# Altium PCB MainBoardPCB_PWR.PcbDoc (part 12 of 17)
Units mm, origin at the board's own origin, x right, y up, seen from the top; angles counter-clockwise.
Board outline 333.63 x 349.38 mm, 16 copper layers (L1, L2 (GND), L3 (Sign), L4 (GND), L5 (Sign), L6 (PWR/GND), L7(PWR/GND), L8 (PWR/GND), L9 (PWR/GND), L10 (PWR/GND), L11 (PWR/GND), L12 (Sign), L13 (GND), L14 (Sign), L15 (GND), L16), stack 2.503 mm thick; 2187 components, 1615 nets, 7987 pads, 1695 vias.
Unrouted connection lines stored in the file: 4757.
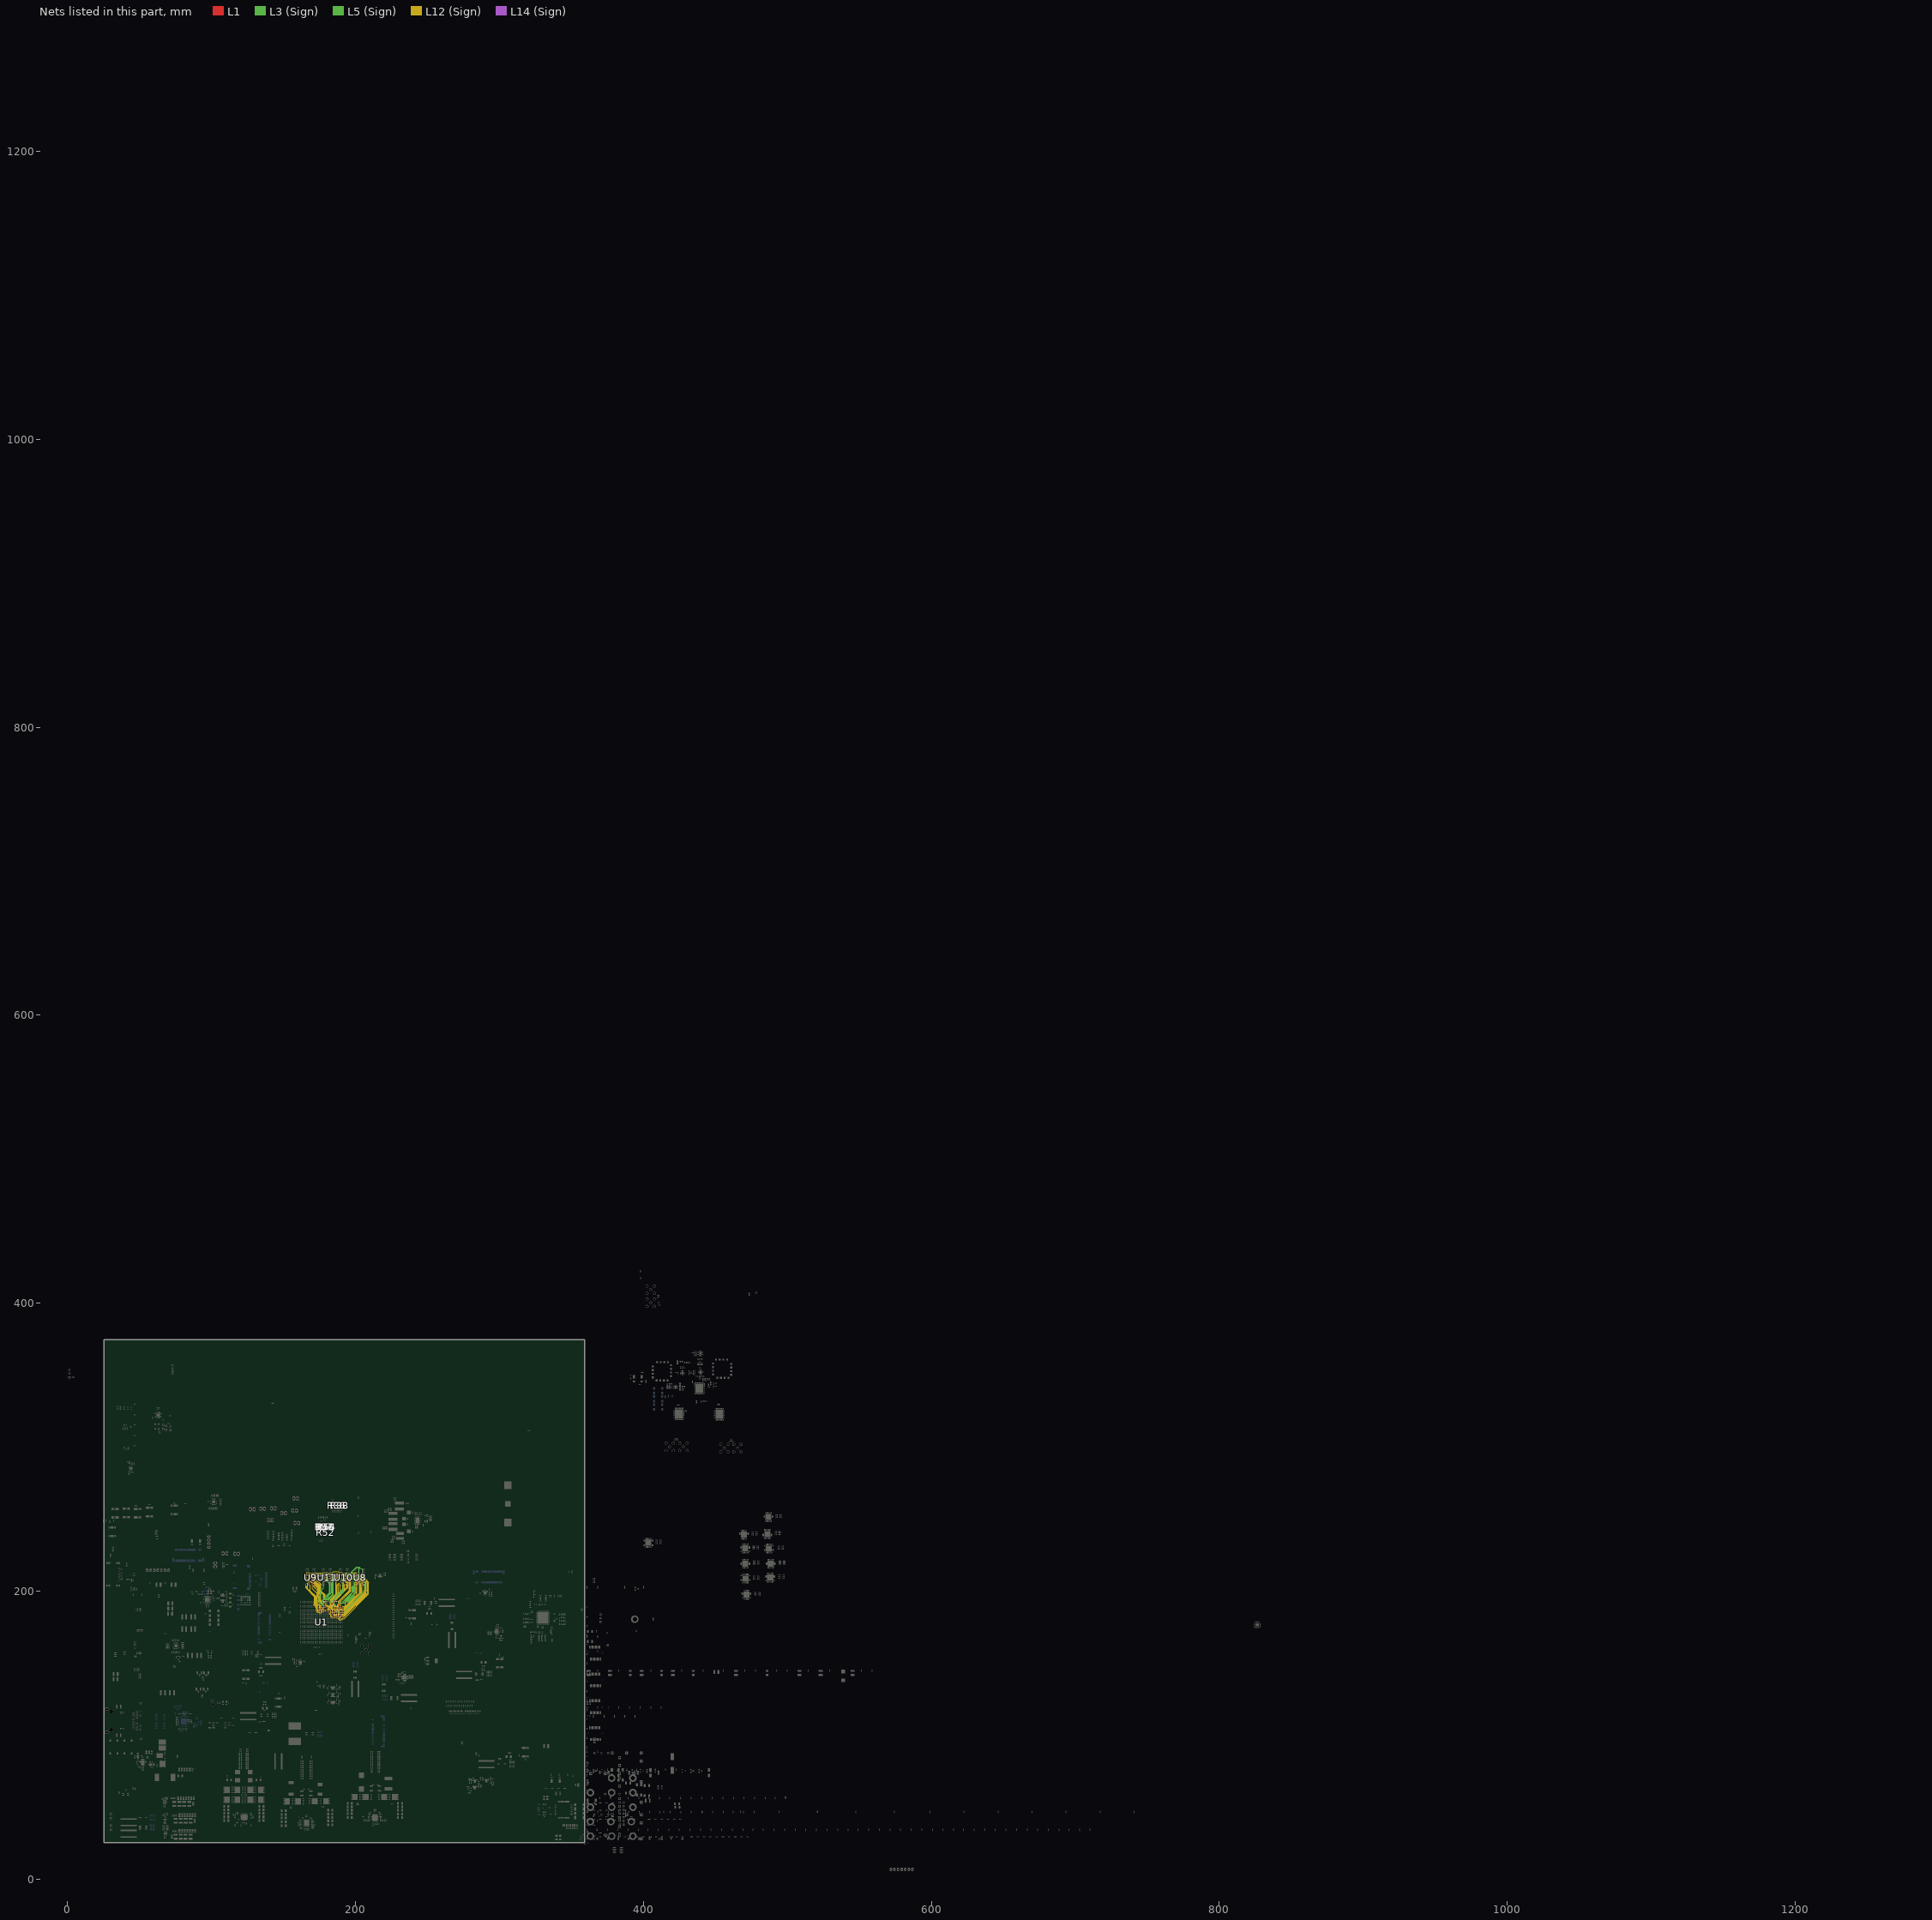
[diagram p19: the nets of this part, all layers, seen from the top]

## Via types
v1: diameter 0.5, hole 0.2, L1 to L16, 786 vias
v2: diameter 0.5/0.35/0.35/0.35/0.35/0.35/0.35/0.35/0.35/0.35/0.35/0.35/0.35/0.35/0.35/0.5 (per signal layer), hole 0.15, L1 to L16, tented both sides, 164 vias
v3: diameter 2.54, hole 1.02, L1 to L16, 152 vias
v4: diameter 0.5/0.35/0.35/0.35/0.35/0.35/0.35/0.35/0.35/0.35/0.35/0.35/0.35/0.35/0.35/0.5 (per signal layer), hole 0.2, L1 to L16, tented both sides, 100 vias
v5: diameter 0.45, hole 0.15, L1 to L16, 79 vias
v6: diameter 0.35/0/0.35 (per signal layer), hole 0.127, L1 to L3 (Sign), tented both sides, 78 vias
v7: diameter 0.45/0.45/0.45/0.45/0.45/0.45/0.45/0.45/0.45/0.45/0.45/0.45/0.45/0.45/0.45/0.45 (per signal layer), hole 0.15, L1 to L16, 65 vias
v8: diameter 0.4, hole 0.15, L1 to L16, 61 vias
v9: diameter 0.2, hole 0.1, L1 to L16, 35 vias
v10: diameter 0.5, hole 0.2, L1 to L16, tented both sides, 32 vias
v11: diameter 0.2/0/0.2 (per signal layer), hole 0.1, L1 to L3 (Sign), 28 vias
v12: diameter 0.4, hole 0.2, L1 to L16, 16 vias
v13: diameter 0.25, hole 0.2, L1 to L16, 16 vias
v14: diameter 0.3, hole 0.2, L1 to L16, 15 vias
v15: diameter 0.5/0.35/0.35/0.35/0.35/0.35/0.35/0.35/0.35/0.35/0.35/0.35/0.35/0.35/0.35/0.45 (per signal layer), hole 0.15, L1 to L16, tented both sides, 10 vias
v16: diameter 5, hole 3, L1 to L16, 9 vias
v17: diameter 0.2/0/0.2 (per signal layer), hole 0.1, L1 to L3 (Sign), tented both sides, 9 vias
v18: diameter 0.35/0/0.35 (per signal layer), hole 0.127, L1 to L3 (Sign), 7 vias
v19: diameter 0.35/0/0.35 (per signal layer), hole 0.127, L14 (Sign) to L16, tented both sides, 5 vias
v20: diameter 1.65, hole 1.65, L1 to L16, 4 vias
v21: diameter 1.15, hole 1.15, L1 to L16, 4 vias
v22: diameter 0.35, hole 0.127, L1 to L2 (GND), 2 vias
v23: diameter 0.4, hole 0.2, L1 to L16, tented both sides, 2 vias
v24: diameter 0.35, hole 0.127, L1 to L2 (GND), tented both sides, 2 vias
v25: diameter 0.508, hole 0.127, L1 to L2 (GND), 2 vias
v26: diameter 0.508, hole 0.127, L2 (GND) to L3 (Sign), 2 vias
v27: diameter 0.35, hole 0.127, L3 (Sign) to L6 (PWR/GND), tented both sides, 2 vias
v28: diameter 0.5, hole 0.2, L3 (Sign) to L6 (PWR/GND), tented both sides, 2 vias
v29: diameter 5.5, hole 3.5, L1 to L16, 1 vias
v30: diameter 0.45/0.45/0.45 (per signal layer), hole 0.15, L1 to L3 (Sign), 1 vias
v31: diameter 0.35/0.35/0.35 (per signal layer), hole 0.127, L1 to L3 (Sign), tented both sides, 1 vias
v32: diameter 0.45/0/0.45 (per signal layer), hole 0.15, L1 to L3 (Sign), tented both sides, 1 vias
v33: diameter 0.45/0/0.45 (per signal layer), hole 0.2, L14 (Sign) to L16, tented both sides, 1 vias
v34: diameter 0.35, hole 0.127, L2 (GND) to L3 (Sign), 1 vias

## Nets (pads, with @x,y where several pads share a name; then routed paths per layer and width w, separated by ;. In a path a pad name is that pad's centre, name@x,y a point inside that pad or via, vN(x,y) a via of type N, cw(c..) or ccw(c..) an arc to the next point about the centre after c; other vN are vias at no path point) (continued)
DDR4_BG0: R36.1 U1.AC28 U8.M2 U9.M2 U10.M2 U11.M2 | length 91.3
  L1 w0.116: U9.M2@171.206,212.248 v2(171.609,212.652) ; U11.M2@182.666,212.248 v2(183.07,212.652) ; v6(183.44,191.414) U1.AC28@183.927,190.927 ; U10.M2@194.127,212.248 v2(194.53,212.652) ; v15(205.215,212.621) U8.M2@205.618,212.217
  L5 (Sign) w0.092: v2(171.609,212.652) 172.737,211.524 178.132,211.524 178.398,211.523 180.823,211.524 181.453,212.153 182.572,212.153 v2(183.07,212.652) 184.198,211.524 192.283,211.524 192.913,212.153 194.032,212.153 v2(194.53,212.652) 195.321,211.861 195.455,211.861 ccw(c195.455,211.951) 195.544,211.951 195.544,212.114 cw(c195.634,212.114) 195.634,212.204 195.903,212.204 cw(c195.903,212.114) 195.992,212.114 195.992,211.861 195.992,211.608 ccw(c196.082,211.608) 196.082,211.519 196.351,211.519 ccw(c196.351,211.608) 196.44,211.608 196.44,211.861 196.44,212.037 cw(c196.53,212.037) 196.53,212.127 196.798,212.127 cw(c196.798,212.037) 196.888,212.037 196.888,211.861 196.888,211.608 ccw(c196.977,211.608) 196.977,211.519 197.246,211.519 ccw(c197.246,211.608) 197.336,211.608 197.336,211.861 197.336,212.037 cw(c197.425,212.037) 197.425,212.127 197.694,212.127 cw(c197.694,212.037) 197.783,212.037 197.783,211.861 197.783,211.608 ccw(c197.873,211.608) 197.873,211.519 198.142,211.519 ccw(c198.142,211.608) 198.231,211.608 198.231,211.861 198.231,212.037 cw(c198.321,212.037) 198.321,212.127 198.59,212.127 cw(c198.59,212.037) 198.679,212.037 198.679,211.861 198.679,211.608 ccw(c198.769,211.608) 198.769,211.519 199.037,211.519 ccw(c199.037,211.608) 199.127,211.608 199.127,211.861 199.127,212.114 cw(c199.216,212.114) 199.216,212.204 199.485,212.204 cw(c199.485,212.114) 199.575,212.114 199.575,211.951 ccw(c199.664,211.951) 199.664,211.861 200.482,211.861 200.495,211.861 200.908,211.448 201.575,211.448 202.15,211.449 202.691,211.989 204.179,211.989 204.81,212.621 v15(205.215,212.621)
  L3 (Sign) w0.092: v6(183.44,191.414) 183.44,191.689 182.917,192.211 182.901,192.227 182.901,192.652 183.202,192.953 183.384,192.953 183.614,193.183 183.857,193.183 185.222,194.548 185.222,194.625 186.168,195.571 186.168,196.559 186.553,196.945 186.693,197.085 186.904,197.296 cw(c186.974,197.225) 187.044,197.296 187.376,196.964 ccw(c187.446,197.034) 187.517,196.964 187.657,197.104 ccw(c187.587,197.174) 187.657,197.245 187.325,197.576 cw(c187.395,197.647) 187.325,197.717 187.465,197.857 cw(c187.536,197.787) 187.606,197.857 187.938,197.525 ccw(c188.008,197.595) 188.078,197.525 188.218,197.666 ccw(c188.148,197.736) 188.218,197.806 187.886,198.138 cw(c187.957,198.208) 187.886,198.278 188.027,198.418 cw(c188.097,198.348) 188.167,198.418 188.499,198.087 ccw(c188.569,198.157) 188.639,198.087 188.78,198.227 ccw(c188.71,198.297) 188.78,198.367 188.448,198.699 cw(c188.518,198.769) 188.448,198.84 188.588,198.98 cw(c188.658,198.91) 188.729,198.98 189.06,198.648 ccw(c189.131,198.718) 189.201,198.648 189.341,198.788 ccw(c189.271,198.859) 189.341,198.929 189.009,199.261 cw(c189.08,199.331) 189.009,199.401 189.22,199.612 189.57,199.962 191.659,202.05 191.659,209.131 192.168,209.64 192.168,209.871 192.392,210.095 192.392,211.28 192.796,211.684 195.732,211.684 200.736,216.687 202.603,216.687 203.263,216.027 203.754,216.027 204.251,215.531 204.433,215.531 205.11,214.853 205.11,212.966 205.151,212.925 205.151,212.684 v15(205.215,212.621)
DDR4_BG1: U1.AC27
DDR4_CAS: R57.1 U1.AJ29 U8.M5 U9.M5 U10.M5 U11.M5 | length 88.9
  L1 w0.116: U9.M5@166.406,212.248 166.802,212.645 v2(166.805,212.645) ; U11.M5@177.866,212.248 178.263,212.645 v2(178.265,212.645) ; U10.M5@189.327,212.248 189.723,212.645 v2(189.726,212.645) ; U1.AJ29@189.927,191.927 v6(190.414,192.414) ; U8.M5@200.787,212.248 200.79,212.248 v2(201.186,212.645)
  L12 (Sign) w0.092: 165.846,213.048 166.25,212.645 v2(166.805,212.645) 167.016,212.645 167.337,212.965 167.738,212.965 168.408,212.295 172.191,212.295 172.541,212.645 v2(178.265,212.645) 178.441,212.645 178.778,212.981 180.241,212.981 180.954,212.268 183.325,212.268 184.594,213.538 188.278,213.538 189.171,212.645 v2(189.726,212.645) 189.937,212.645 190.258,212.965 190.659,212.965 191.329,212.295 193.357,212.295 193.815,212.295 ccw(c193.815,212.384) 193.905,212.384 193.905,212.391 cw(c193.995,212.391) 193.995,212.48 194.263,212.48 cw(c194.263,212.391) 194.353,212.391 194.353,212.384 ccw(c194.442,212.384) 194.442,212.295 194.577,212.295 196.583,212.295 197.509,212.295 ccw(c197.509,212.384) 197.598,212.384 197.598,212.469 cw(c197.688,212.469) 197.688,212.558 197.957,212.558 cw(c197.957,212.469) 198.046,212.469 198.046,212.295 198.046,212.265 ccw(c198.136,212.265) 198.136,212.175 198.404,212.175 ccw(c198.404,212.265) 198.494,212.265 198.494,212.295 198.494,212.469 cw(c198.584,212.469) 198.584,212.558 198.852,212.558 cw(c198.852,212.469) 198.942,212.469 198.942,212.295 198.942,212.265 ccw(c199.031,212.265) 199.031,212.175 199.3,212.175 ccw(c199.3,212.265) 199.39,212.265 199.39,212.295 199.39,212.469 cw(c199.479,212.469) 199.479,212.558 199.748,212.558 cw(c199.748,212.469) 199.837,212.469 199.837,212.295 199.837,212.265 ccw(c199.927,212.265) 199.927,212.175 200.196,212.175 ccw(c200.196,212.265) 200.285,212.265 cw(c200.315,212.265) 200.315,212.295 200.509,212.295 200.859,212.645 v2(201.186,212.645)
  L3 (Sign) w0.092: v6(190.414,192.414) 191.268,192.414 191.331,192.477 198.417,199.563 198.514,199.661 198.514,199.76 ccw(c198.414,199.76) 198.414,199.859 197.577,199.859 cw(c197.577,199.958) 197.478,199.958 197.478,200.157 cw(c197.577,200.157) 197.577,200.256 198.514,200.256 199.305,200.256 ccw(c199.305,200.355) 199.404,200.355 199.404,200.554 ccw(c199.305,200.554) 199.305,200.653 198.514,200.653 197.577,200.653 cw(c197.577,200.752) 197.478,200.752 197.478,200.951 cw(c197.577,200.951) 197.577,201.05 198.514,201.05 199.567,201.05 ccw(c199.567,201.149) 199.666,201.149 199.666,201.348 ccw(c199.567,201.348) 199.567,201.447 198.514,201.447 197.577,201.447 cw(c197.577,201.546) 197.478,201.546 197.478,201.745 cw(c197.577,201.745) 197.577,201.844 198.514,201.844 199.567,201.844 ccw(c199.567,201.943) 199.666,201.943 199.666,202.142 ccw(c199.567,202.142) 199.567,202.241 198.514,202.241 197.577,202.241 cw(c197.577,202.34) 197.478,202.34 197.478,202.539 cw(c197.577,202.539) 197.577,202.638 198.514,202.638 199.567,202.638 ccw(c199.567,202.737) 199.666,202.737 199.666,202.936 ccw(c199.567,202.936) 199.567,203.035 198.514,203.035 197.577,203.035 cw(c197.577,203.134) 197.478,203.134 197.478,203.333 cw(c197.577,203.333) 197.577,203.432 198.514,203.432 199.54,203.432 ccw(c199.54,203.531) 199.639,203.531 199.639,203.73 ccw(c199.54,203.73) 199.54,203.829 198.545,203.829 cw(c198.545,203.86) 198.514,203.86 198.514,210.696 200.462,212.645 v2(201.186,212.645)
DDR4_CK0: U1.AE30
DDR4_CK1: U1.AF28
DDR4_CK_N: R52.1 U1.AF30 U8.K5 U9.K5 U10.K5 U11.K5 | length 88
  L1 w0.1: U1.AF30@186.927,192.927 187.4,192.454 v23(187.4,192.341) ; U8.K5@200.787,210.648 v2@201.184,210.251
  L1 w0.116: U9.K5@166.406,210.648 v2(166.809,210.244) ; U11.K5@177.866,210.648 v2(178.27,210.244) ; U10.K5@189.327,210.648 v2(189.73,210.244) ; v2(201.184,210.249) v2@201.184,210.251
  L5 (Sign) w0.1: v23@187.4,192.254 ccw(c187.619,192.254) 187.619,192.035 191.927,192.035 191.935,192.026 ; 198.704,198.196 199.002,198.494 ccw(c197.206,200.29) 199.746,200.29 199.746,206.887 cw(c202.498,206.887) 200.552,208.833 201.383,209.664 ccw(c201.2,209.848) 201.459,209.848 ccw(c201.156,209.848) 201.37,210.062 v2(201.184,210.249)
  L5 (Sign) w0.12: 191.935,192.026 192.303,192.026 ccw(c192.303,192.584) 192.697,192.189 193.106,192.598 ccw(c192.975,192.729) 193.16,192.729 ccw(c192.975,192.729) 193.106,192.86 192.587,193.379 cw(c192.882,193.674) 192.587,193.969 192.77,194.151 cw(c193.064,193.857) 193.359,194.151 194.823,192.687 ccw(c194.954,192.818) 195.085,192.687 195.268,192.87 ccw(c195.137,193.001) 195.322,193.001 ccw(c195.137,193.001) 195.268,193.132 193.804,194.596 cw(c194.098,194.891) 193.804,195.185 193.986,195.368 cw(c194.281,195.073) 194.576,195.368 196.04,193.904 ccw(c196.171,194.035) 196.302,193.904 196.484,194.086 ccw(c196.353,194.217) 196.538,194.217 ccw(c196.353,194.217) 196.484,194.348 195.02,195.812 cw(c195.315,196.107) 195.02,196.402 195.203,196.584 cw(c195.497,196.289) 195.792,196.584 197.256,195.12 ccw(c197.387,195.251) 197.518,195.12 197.701,195.303 ccw(c197.57,195.434) 197.755,195.434 ccw(c197.57,195.434) 197.701,195.565 196.237,197.029 cw(c196.531,197.324) 196.237,197.618 196.419,197.801 cw(c196.714,197.506) 197.009,197.801 198.473,196.337 ccw(c198.604,196.468) 198.735,196.337 198.917,196.519 ; 198.704,198.196 198.398,197.89 ccw(c198.693,197.595) 198.398,197.3 198.917,196.781 cw(c198.786,196.65) 198.971,196.65 cw(c198.786,196.65) 198.917,196.519
  L12 (Sign) w0.1: v2(166.809,210.244) v2@166.864,210.244
  L14 (Sign) w0.1: v2(166.809,210.244) 166.809,210.307 cw(c167.03,210.307) 167.03,210.528 167.55,210.528 ccw(c167.55,211.55) 168.273,210.827 168.449,211.003 cw(c170.245,209.207) 170.245,211.747 172.75,211.747 cw(c172.75,210.062) 173.941,211.254 ccw(c175.704,213.016) 175.704,210.524 177.991,210.524 cw(c177.991,210.244) v2(178.27,210.244) 178.27,210.355 cw(c178.448,210.355) 178.448,210.533 178.805,210.533 ccw(c178.805,212.074) 179.895,210.984 180.119,211.209 cw(c181.051,210.276) 181.051,211.595 183.26,211.595 cw(c183.26,209.055) 185.056,210.851 185.112,210.795 ccw(c185.766,211.449) 185.766,210.524 189.451,210.524 cw(c189.451,210.244) v2(189.73,210.244) 189.73,210.355 cw(c189.903,210.355) 189.903,210.528 190.969,210.528 ccw(c190.969,211.848) 191.903,210.914 192.557,211.569 cw(c193.108,211.018) 193.108,211.798 195.007,211.798 cw(c195.007,210.195) 196.141,211.328 196.143,211.326 ccw(c197.272,212.455) 197.272,210.858 199.049,210.858 199.302,210.858 199.632,210.858 cw(c199.632,210.681) 199.809,210.681 199.809,210.625 ccw(c199.986,210.625) 199.986,210.448 200.138,210.448 ccw(c200.138,210.625) 200.316,210.625 200.316,210.681 cw(c200.493,210.681) 200.493,210.858 200.822,210.858 201.329,210.858 201.345,210.858 cw(c201.345,210.744) 201.459,210.744 201.459,210.525 cw(c201.184,210.525) v2(201.184,210.249)
DDR4_CK_P: R54.1 U1.AG28 U8.K4 U9.K4 U10.K4 U11.K4 | length 88.2
  L1 w0.1: v23(187.427,191.567) 187.427,191.427 U1.AG28@187.927,190.927 ; U8.K4@201.587,210.648 v2@201.984,210.251
  L1 w0.116: v2(166.802,211.052) U9.K4@167.206,210.648 ; v2(178.263,211.052) U11.K4@178.666,210.648 ; v2(189.723,211.052) U10.K4@190.127,210.648 ; v2(201.984,210.249) v2@201.984,210.251
  L5 (Sign) w0.1: v23@187.447,191.587 v23(187.427,191.567) cw(c187.646,191.567) 187.646,191.786 191.927,191.786 191.935,191.794 ; 198.856,198.019 199.152,198.315 ccw(c197.206,200.261) 199.958,200.261 199.958,206.835 cw(c202.498,206.835) 200.702,208.631 201.56,209.49 ccw(c201.204,209.846) 201.708,209.846 201.708,209.848 cw(c202.011,209.848) 201.797,210.062 v2(201.984,210.249)
  L5 (Sign) w0.12: 191.935,191.794 192.304,191.794 ccw(c192.304,192.581) 192.861,192.025 193.27,192.434 ccw(c192.975,192.729) 193.392,192.729 ccw(c192.975,192.729) 193.27,193.024 192.751,193.543 cw(c192.882,193.674) 192.751,193.805 192.934,193.987 cw(c193.064,193.857) 193.195,193.987 194.659,192.523 ccw(c194.954,192.818) 195.249,192.523 195.432,192.706 ccw(c195.137,193.001) 195.554,193.001 ccw(c195.137,193.001) 195.432,193.296 193.968,194.76 cw(c194.098,194.891) 193.968,195.021 194.15,195.204 cw(c194.281,195.073) 194.412,195.204 195.876,193.74 ccw(c196.171,194.035) 196.466,193.74 196.648,193.922 ccw(c196.353,194.217) 196.77,194.217 ccw(c196.353,194.217) 196.648,194.512 195.184,195.976 cw(c195.315,196.107) 195.184,196.238 195.367,196.42 cw(c195.497,196.289) 195.628,196.42 197.092,194.956 ccw(c197.387,195.251) 197.682,194.956 197.865,195.139 ccw(c197.57,195.434) 197.987,195.434 ccw(c197.57,195.434) 197.865,195.729 196.401,197.193 cw(c196.531,197.324) 196.401,197.454 196.583,197.637 cw(c196.714,197.506) 196.845,197.637 198.309,196.173 ccw(c198.604,196.468) 198.899,196.173 199.081,196.355 ccw(c198.786,196.65) 199.203,196.65 ccw(c198.786,196.65) 199.081,196.945 198.562,197.464 cw(c198.693,197.595) 198.562,197.726 198.856,198.019
  L14 (Sign) w0.1: v2(166.802,211.052) 166.802,211.005 ccw(c167.03,211.005) 167.03,210.777 167.548,210.777 ccw(c167.548,211.556) 168.099,211.005 168.275,211.181 cw(c170.242,209.214) 170.242,211.996 172.75,211.996 cw(c172.75,210.062) 174.117,211.43 ccw(c175.704,213.016) 175.704,210.772 177.984,210.772 ccw(c177.984,211.052) v2(178.263,211.052) 178.263,210.967 ccw(c178.448,210.967) 178.448,210.782 178.804,210.782 ccw(c178.804,212.076) 179.72,211.161 179.944,211.386 cw(c181.05,210.28) 181.05,211.844 183.262,211.844 cw(c183.262,209.06) 185.23,211.028 185.286,210.972 ccw(c185.769,211.455) 185.769,210.772 189.444,210.772 ccw(c189.444,211.052) v2(189.723,211.052) 189.723,210.957 ccw(c189.903,210.957) 189.903,210.777 190.967,210.777 ccw(c190.967,211.854) 191.728,211.092 192.382,211.746 cw(c193.108,211.02) 193.108,212.046 195.009,212.046 cw(c195.009,210.2) 196.315,211.505 196.317,211.504 ccw(c197.275,212.463) 197.275,211.107 201.345,211.107 cw(c201.345,210.744) 201.708,210.744 201.708,210.525 ccw(c201.984,210.525) v2(201.984,210.249)
DDR4_CKE0: R38.1 U1.AC30 U8.K2 U9.K2 U10.K2 U11.K2 | length 92.8
  L1 w0.116: U9.K2@171.206,210.648 v2(171.609,210.244) ; U11.K2@182.666,210.648 v2(183.07,210.244) ; U1.AC30@183.927,192.927 v6(184.414,192.44) ; U10.K2@194.127,210.648 v2(194.53,210.244) ; U8.K2@205.587,210.648 v15(205.991,210.244)
  L5 (Sign) w0.092: v2(171.609,210.244) 172.185,210.82 172.355,210.82 174.401,208.774 179.645,208.774 179.683,208.812 179.961,208.812 181.017,209.867 182.178,209.867 182.555,210.244 v2(183.07,210.244) 183.799,210.244 185.81,208.233 190.761,208.233 191.403,208.875 191.426,208.875 192.034,209.484 192.359,209.484 192.743,209.867 193.505,209.867 193.882,210.244 v2(194.53,210.244) 194.53,210.012 196.084,208.458 196.977,208.458 197.527,208.458 ccw(c197.527,208.547) 197.616,208.547 197.616,208.726 cw(c197.706,208.726) 197.706,208.816 197.974,208.816 cw(c197.974,208.726) 198.064,208.726 198.064,208.458 198.064,208.189 ccw(c198.154,208.189) 198.154,208.1 198.422,208.1 ccw(c198.422,208.189) 198.512,208.189 198.512,208.458 198.512,208.726 cw(c198.601,208.726) 198.601,208.816 198.87,208.816 cw(c198.87,208.726) 198.96,208.726 198.96,208.458 198.96,208.189 ccw(c199.049,208.189) 199.049,208.1 199.318,208.1 ccw(c199.318,208.189) 199.407,208.189 199.407,208.368 cw(c199.497,208.368) 199.497,208.458 199.631,208.458 199.946,208.773 199.946,209.546 201.038,210.638 202.906,210.638 203.676,209.867 205.614,209.867 v15(205.991,210.244)
  L3 (Sign) w0.092: v6(184.414,192.44) 184.414,191.919 185.761,190.573 185.761,190.307 185.387,189.933 185.208,189.933 185.034,189.759 185.034,188.295 185.352,187.977 185.698,187.977 188.289,185.387 191.942,185.387 191.98,185.425 191.988,185.425 205.327,198.764 205.327,199.974 206.58,201.227 206.58,203.403 206.58,203.502 ccw(c206.48,203.502) 206.48,203.602 206.409,203.602 cw(c206.409,203.701) 206.31,203.701 206.31,203.899 cw(c206.409,203.899) 206.409,203.999 206.48,203.999 ccw(c206.48,204.098) 206.58,204.098 206.58,204.296 ccw(c206.48,204.296) 206.48,204.396 205.88,204.396 cw(c205.88,204.495) 205.781,204.495 205.781,204.693 cw(c205.88,204.693) 205.88,204.793 206.48,204.793 ccw(c206.48,204.892) 206.58,204.892 206.58,205.067 206.58,205.265 206.58,205.563 ccw(c206.48,205.563) 206.48,205.662 206.404,205.662 cw(c206.404,205.762) 206.305,205.762 206.305,205.96 cw(c206.404,205.96) 206.404,206.059 206.48,206.059 ccw(c206.48,206.159) 206.58,206.159 206.58,206.357 ccw(c206.48,206.357) 206.48,206.456 206.415,206.456 cw(c206.415,206.556) 206.316,206.556 206.316,206.754 cw(c206.415,206.754) 206.415,206.853 206.48,206.853 ccw(c206.48,206.953) 206.58,206.953 206.58,207.061 206.58,209.655 v15(205.991,210.244)
DDR4_CKE1: U1.AB28
DDR4_CS_B: R46.1 U1.AD30 U8.L4 U9.L4 U10.L4 U11.L4 | length 89.5
  L1 w0.116: U9.L4@167.206,211.448 167.602,211.844 v2(167.605,211.844) ; U11.L4@178.666,211.448 179.063,211.845 v2(179.065,211.845) ; U1.AD30@184.927,192.927 v6(185.414,193.414) ; U10.L4@190.127,211.448 190.523,211.844 v2(190.526,211.844) ; U8.L4@201.587,211.448 201.984,211.845 v1(201.986,211.845)
  L12 (Sign) w0.092: 165.92,211.844 166.258,211.506 167.266,211.506 v2(167.605,211.844) 167.766,211.684 177.714,211.684 177.949,211.448 178.669,211.448 v2(179.065,211.845) 179.29,211.62 185.09,211.62 185.635,212.165 188.52,212.165 189.179,211.506 190.187,211.506 v2(190.526,211.844) 190.991,211.379 191.791,210.579 193.129,210.579 193.434,210.883 194.005,210.883 194.221,210.668 197.333,210.668 199.152,210.668 cw(c199.152,210.578) 199.242,210.578 199.242,210.267 ccw(c199.331,210.267) 199.331,210.178 199.6,210.178 ccw(c199.6,210.267) 199.69,210.267 199.69,210.578 cw(c199.779,210.578) 199.779,210.668 200.048,210.668 cw(c200.048,210.578) 200.137,210.578 200.137,210.428 ccw(c200.227,210.428) 200.227,210.338 200.496,210.338 ccw(c200.496,210.428) 200.585,210.428 200.585,210.578 cw(c200.675,210.578) 200.675,210.668 200.809,210.668 201.52,211.379 v1(201.986,211.845)
  L3 (Sign) w0.092: v6(185.414,193.414) 185.414,194.546 189.573,198.704 cw(c189.622,198.655) 189.67,198.704 190.154,198.221 ccw(c190.224,198.291) 190.294,198.221 190.435,198.361 ccw(c190.364,198.431) 190.435,198.501 189.902,199.034 189.547,199.389 cw(c189.617,199.459) 189.547,199.53 189.687,199.67 cw(c189.757,199.6) 189.827,199.67 190.183,199.314 190.715,198.782 ccw(c190.785,198.852) 190.856,198.782 190.996,198.923 ccw(c190.926,198.993) 190.996,199.063 190.464,199.595 190.108,199.951 cw(c190.178,200.021) 190.108,200.091 190.249,200.231 cw(c190.319,200.161) 190.389,200.231 190.745,199.876 191.277,199.344 ccw(c191.347,199.414) 191.417,199.344 191.557,199.484 ccw(c191.487,199.554) 191.557,199.624 191.025,200.157 190.67,200.512 cw(c190.74,200.582) 190.67,200.653 190.81,200.793 cw(c190.88,200.723) 190.95,200.793 191.306,200.437 191.633,200.11 ccw(c191.703,200.18) 191.774,200.11 191.914,200.25 ccw(c191.844,200.321) 191.914,200.391 191.657,200.648 cw(c191.727,200.718) 191.657,200.788 191.727,200.858 191.851,200.982 191.851,209.051 192.36,209.561 192.36,209.678 192.602,209.92 192.602,211.177 192.614,211.189 192.614,211.2 192.777,211.364 192.788,211.364 192.79,211.365 192.793,211.365 192.895,211.468 195.788,211.468 200.793,216.473 201.84,216.473 202.587,215.725 202.587,213.593 202.348,213.353 202.348,213.287 202.233,213.173 202.233,212.851 202.307,212.777 202.307,212.512 202.233,212.438 202.233,212.092 v1(201.986,211.845)
DDR4_CS_N1: U1.AD29
DDR4_DM0: U1.AJ20 U8.E2 | length 33.5
  L1 w0.116: U1.AJ20@189.927,182.927 v2(190.331,182.523) ; U8.E2@205.587,206.648 v2(205.991,207.052)
  L12 (Sign) w0.092: v2(190.331,182.523) 190.598,182.791 190.598,182.87 190.847,183.119 191.225,183.119 191.602,183.119 207.058,198.574 207.058,204.979 207.08,205 207.08,205.903 205.991,206.992 v2(205.991,207.052)
DDR4_DM1: U1.AJ25 U8.E4 | length 27
  L1 w0.116: U1.AJ25@189.927,187.927 v4(190.414,188.414) ; U8.E4@201.587,206.648 v2(201.991,207.052)
  L12 (Sign) w0.092: v4(190.414,188.414) 190.916,188.414 191.231,188.1 191.275,188.1 191.281,188.093 191.547,188.093 191.554,188.1 192.138,188.1 202.827,198.789 202.827,206.397 202.173,207.052 v2(201.991,207.052)
DDR4_DM2: U1.AF21 U10.E2 | length 31.2
  L1 w0.116: v4(186.44,184.414) U1.AF21@186.927,183.927 ; U10.E2@194.127,206.648 v2(194.53,207.052)
  L12 (Sign) w0.092: v4(186.44,184.414) 186.791,184.063 187.49,184.063 187.546,184.119 187.547,184.119 187.735,184.307 187.735,184.308 188.337,184.909 188.337,185.811 187.337,186.811 187.337,188.876 185.344,190.868 185.344,192.82 194.92,202.396 194.92,206.662 v2(194.53,207.052)
DDR4_DM3: U1.AE25 U10.E4 | length 24.3
  L1 w0.116: v4(185.44,188.414) U1.AE25@185.927,187.927 ; U10.E4@190.127,206.648 v2(190.53,206.244)
  L12 (Sign) w0.092: v4(185.44,188.414) 185.028,188.002 184.292,188.002 184.044,188.25 184.044,190.268 184,190.312 184,190.494 183.989,190.505 183.989,192.593 184,192.604 184,193.418 191.275,200.693 191.275,200.96 191.302,200.987 191.302,205.473 v2(190.53,206.244)
DDR4_DM4: U1.Y24 U9.E2 | length 26.2
  L1 w0.116: v2(170.802,206.244) U9.E2@171.206,206.648 ; v10(180.44,186.44) U1.Y24@180.927,186.927
  L12 (Sign) w0.092: v2(170.802,206.244) 171.06,206.244 174.864,202.441 174.864,198.427 175.692,197.599 175.692,193.586 176.173,193.105 176.173,191.605 177.316,190.462 177.316,188.241 178.018,187.539 178.018,187.25 178.25,187.018 178.578,187.018 178.654,187.094 179.225,187.094 179.342,186.977 179.596,186.977 180.133,186.44 v10(180.44,186.44)
DDR4_DM5: U1.R24 U9.E4 | length 27.3
  L1 w0.116: U9.E4@167.206,206.648 v2(167.609,206.244) ; U1.R24@175.927,186.927 v10(176.414,187.414)
  L12 (Sign) w0.092: v2(167.609,206.244) 166.648,205.283 166.648,201.508 172.11,196.045 172.11,191.401 172.415,191.097 172.415,190.005 173.371,189.049 173.371,186.977 173.759,186.588 174.231,186.588 174.663,187.02 175.704,187.02 176.099,187.414 v10(176.414,187.414)
DDR4_DM6: U1.V28 U11.E2 | length 19.8
  L1 w0.116: v6(178.44,191.414) U1.V28@178.927,190.927 ; U11.E2@182.666,206.648 183.063,206.252 v6(183.063,206.249)
  L3 (Sign) w0.092: v6(178.44,191.414) 178.44,191.813 178.854,192.227 178.854,192.621 178.625,192.85 178.141,192.85 177.895,193.096 177.895,193.62 178.202,193.927 178.624,193.927 183.595,198.898 183.595,205.719 183.592,205.719 v6(183.063,206.249)
DDR4_DM7: U1.P28 U11.E4 | length 19.6
  L1 w0.116: v6(174.44,191.414) U1.P28@174.927,190.927 ; v6(178.27,207.047) 178.27,207.044 U11.E4@178.666,206.648
  L3 (Sign) w0.092: v6(174.44,191.414) 173.779,191.414 173.531,191.662 173.531,193.351 175.832,195.651 175.832,200.16 177.866,202.195 177.866,206.643 v6(178.27,207.047)
DDR4_DM8: U1.AA27
DDR4_DQ0: U1.AH22 U8.G2 | length 46.8
  L1 w0.116: U1.AH22@188.927,184.927 v4(189.414,184.44) ; U8.G2@205.587,208.248 v2(205.991,208.652)
  L12 (Sign) w0.092: v4(189.414,184.44) 188.659,183.684 188.659,183.406 187.844,182.591 187.844,182.586 187.795,182.537 187.795,181.059 188.603,180.251 189.068,180.251 189.276,180.044 189.604,180.044 189.724,180.164 190.336,180.164 191.059,180.886 191.999,180.886 209.08,197.968 209.08,206.25 206.678,208.652 v2(205.991,208.652)
DDR4_DQ1: U1.AH21 U8.F4 | length 39.2
  L1 w0.116: U1.AH21@188.927,183.927 v4(189.414,183.44) ; v2(201.184,207.852) U8.F4@201.587,207.448
  L12 (Sign) w0.092: v4(189.414,183.44) 190.099,184.125 190.275,184.125 190.281,184.119 190.547,184.119 190.553,184.125 191.275,184.125 191.281,184.119 191.547,184.119 191.598,184.169 191.637,184.169 206.591,199.123 206.591,205.055 206.696,205.16 206.696,205.744 205.901,206.539 205.718,206.539 205.226,207.031 205.144,207.031 204.645,207.531 204.251,207.531 204.063,207.719 203.584,207.719 202.337,208.965 201.858,208.965 201.184,208.291 v2(201.184,207.852)
DDR4_DQ2: U1.AJ22 U8.H3 | length 45.3
  L1 w0.116: U1.AJ22@189.927,184.927 v4(190.414,184.44) ; v2(204.384,209.452) U8.H3@204.787,209.048
  L12 (Sign) w0.092: v4(190.414,184.44) 189.926,184.44 189.421,183.934 189.192,183.934 188.85,183.593 188.85,183.326 188.036,182.512 188.036,181.216 188.326,180.927 188.852,180.927 190.068,182.143 190.503,182.143 191.01,182.65 191.01,182.656 191.198,182.844 191.464,182.844 191.501,182.881 191.868,182.881 207.25,198.263 207.25,204.899 207.272,204.921 207.272,205.982 206.362,206.892 206.362,207.135 206.081,207.415 205.303,207.415 204.897,207.822 204.897,208.593 204.384,209.106 v2(204.384,209.452)
DDR4_DQ3: U1.AK22 U8.H4 | length 34.5
  L1 w0.116: U1.AK22@190.927,184.927 v4(191.414,184.44) ; U8.H4@201.587,209.048 v2(201.991,208.644)
  L12 (Sign) w0.092: v4(191.414,184.44) 206.399,199.424 206.399,205.134 206.504,205.239 206.504,205.664 205.821,206.347 205.639,206.347 205.146,206.839 205.065,206.839 204.576,207.327 203.308,207.327 v2(201.991,208.644)
DDR4_DQ4: U1.AK20 U8.H2 | length 36.6
  L1 w0.116: U1.AK20@190.927,182.927 v2(191.331,182.523) ; v2(205.184,209.452) U8.H2@205.587,209.048
  L12 (Sign) w0.092: v2(191.331,182.523) 192.023,182.523 207.442,197.942 207.442,204.82 207.464,204.841 207.464,206.062 206.565,206.96 206.565,207.234 206.192,207.607 205.44,207.607 205.39,207.656 205.386,207.656 205.089,207.953 205.089,208.96 205.184,209.055 v2(205.184,209.452)
DDR4_DQ5: U1.AJ19 U8.H5 | length 44.5
  L1 w0.116: U1.AJ19@189.927,181.927 v2(190.331,181.523) ; v2(200.384,209.452) U8.H5@200.787,209.048
  L12 (Sign) w0.092: v2(190.331,181.523) 190.655,181.523 191.148,182.016 191.546,182.016 191.861,182.331 192.103,182.331 207.634,197.863 207.634,198.104 208.358,198.828 208.358,199.097 208.369,199.108 208.369,199.695 207.656,200.408 207.656,206.415 206.223,207.848 205.465,207.848 205.296,208.018 205.296,208.776 205.505,208.985 205.505,209.585 205.241,209.848 202.641,209.848 202.457,209.664 202.275,209.664 202.25,209.639 202.124,209.765 201.858,209.765 201.795,209.702 200.634,209.702 v2(200.384,209.452)
DDR4_DQ6: U1.AK19 U8.J3 | length 40.6
  L1 w0.116: U1.AK19@190.927,181.927 v2(191.331,181.523) ; v2(204.251,210.312) 204.323,210.312 204.387,210.248 U8.J3@204.787,209.848
  L12 (Sign) w0.092: v2(191.331,181.523) 191.531,181.724 191.721,181.913 191.934,181.913 192.16,182.139 192.182,182.139 207.826,197.783 207.826,197.805 208.561,198.541 208.561,205.795 206.318,208.039 206.304,208.039 206.302,208.04 205.795,208.04 205.587,208.248 205.587,208.796 205.697,208.906 205.697,209.664 205.614,209.747 205.614,210.337 205.393,210.557 204.689,210.557 204.38,210.248 204.317,210.312 v2(204.251,210.312)
DDR4_DQ7: U1.AH19 U8.J4 | length 41
  L1 w0.116: v4(188.44,181.44) U1.AH19@188.927,181.927 ; U8.J4@201.587,209.848 v2(201.991,209.444)
  L12 (Sign) w0.092: v4(188.44,181.44) 189.029,181.44 189.865,182.275 189.865,183.455 190.221,183.811 191.646,183.811 206.866,199.03 206.866,205.058 206.888,205.08 206.888,205.823 205.98,206.731 205.798,206.731 205.305,207.223 205.224,207.223 204.705,207.742 204.705,207.985 204.516,208.173 204.251,208.173 204.218,208.14 203.67,208.14 203.251,208.559 202.366,209.444 v2(201.991,209.444)
DDR4_DQ8: U1.AH23 U8.A3 | length 25.4
  L1 w0.116: U1.AH23@188.927,185.927 v4(189.414,186.414) ; v2(204.384,203.044) U8.A3@204.787,203.448
  L12 (Sign) w0.092: v4(189.414,186.414) 189.871,186.871 191.687,186.871 191.847,187.03 192.265,187.03 204.384,199.149 v2(204.384,203.044)
DDR4_DQ9: U1.AK23 U8.B5 | length 39.3
  L1 w0.116: U1.AK23@190.927,185.927 v4(191.414,186.414) ; v2(200.384,203.844) U8.B5@200.787,204.248
  L12 (Sign) w0.092: v4(191.414,186.414) 192.703,186.414 204.705,198.416 204.705,203.711 206.312,205.319 206.312,205.585 205.742,206.155 205.559,206.155 205.067,206.647 204.985,206.647 204.659,206.973 203.066,206.973 202.283,207.757 201.572,207.757 201.251,207.436 201.251,206.724 201.528,206.447 201.528,206.146 201.505,206.123 201.505,206.119 201.408,206.022 201.408,205.94 201.316,205.848 200.971,205.848 200.596,206.223 200.201,206.223 199.798,205.819 199.798,204.834 200.384,204.249 v2(200.384,203.844)
DDR4_DQ10: U1.AG24 U8.C3 | length 27.9
  L1 w0.116: U1.AG24@187.927,186.927 187.93,186.927 v4(188.43,187.427) ; v2(204.384,204.644) U8.C3@204.787,205.048
  L12 (Sign) w0.092: v4(188.43,187.427) 188.951,186.906 189.574,186.906 189.731,187.063 191.555,187.063 191.715,187.222 192.185,187.222 204.02,199.057 204.02,204.281 v2(204.384,204.644)
DDR4_DQ11: U1.AK24 U8.C4 | length 32.4
  L1 w0.116: U1.AK24@190.927,186.927 v4(191.414,187.414) ; U8.C4@201.587,205.048 v2(201.991,205.452)
  L12 (Sign) w0.092: v4(191.414,187.414) 192.106,187.414 203.721,199.03 203.721,204.521 204.935,205.735 204.935,206.154 204.5,206.589 202.907,206.589 202.124,207.373 201.783,207.373 201.635,207.224 201.635,206.937 201.841,206.731 202.171,206.731 202.548,206.354 202.548,206.009 v2(201.991,205.452)
DDR4_DQ12: U1.AJ26 U8.C2 | length 32.1
  L1 w0.116: U1.AJ26@189.927,188.927 v4(190.414,189.414) ; U8.C2@205.587,205.048 v2(205.991,205.452)
  L12 (Sign) w0.092: v4(190.414,189.414) 192.297,189.414 193.04,190.157 193.04,191.427 200.474,198.861 200.474,203.281 200.708,203.515 200.708,204.327 199.99,205.045 199.99,205.572 200.191,205.773 200.562,205.773 200.711,205.624 201.363,205.624 201.748,206.009 201.748,206.499 201.443,206.804 201.443,207.304 201.704,207.565 202.203,207.565 202.986,206.781 204.579,206.781 204.906,206.455 204.987,206.455 205.48,205.963 v2(205.991,205.452)
DDR4_DQ13: U1.AK25 U8.C5 | length 22.9
  L1 w0.116: U1.AK25@190.927,187.927 v4(191.414,188.414) ; v2(200.384,205.452) U8.C5@200.787,205.048
  L12 (Sign) w0.092: v4(191.414,188.414) 192.018,188.414 200.99,197.387 200.99,204.845 v2(200.384,205.452)
DDR4_DQ14: U1.AG25 U8.D3 | length 28.9
  L1 w0.116: U1.AG25@187.927,187.927 187.933,187.927 188.43,188.424 v4(188.43,188.455) ; v2(204.384,206.252) U8.D3@204.787,205.848
  L12 (Sign) w0.092: v4(188.43,188.455) 189.154,187.731 189.277,187.731 189.281,187.735 192.155,187.735 203.529,199.109 203.529,205.397 v2(204.384,206.252)
DDR4_DQ15: U1.AH26 U8.D4 | length 24
  L1 w0.116: U1.AH26@188.927,188.927 v4(189.414,189.414) ; v2(201.184,206.252) U8.D4@201.587,205.848
  L12 (Sign) w0.092: v4(189.414,189.414) 189.414,190.561 199.606,200.753 199.606,206.075 200.033,206.502 200.933,206.502 v2(201.184,206.252)
DDR4_DQ16: U1.AD22 U10.G2 | length 34.4
  L1 w0.116: v4(184.44,184.44) U1.AD22@184.927,184.927 ; U10.G2@194.127,208.248 v2(194.53,208.652)
  L12 (Sign) w0.092: v4(184.44,184.44) 185.085,183.794 187.493,183.794 187.625,183.927 187.627,183.927 187.927,184.227 187.927,184.229 188.529,184.83 188.529,185.891 187.529,186.891 187.529,190.641 187.901,191.014 187.901,192.843 195.567,200.508 195.567,208.204 195.12,208.652 v2(194.53,208.652)
DDR4_DQ17: U1.AE22 U10.F4 | length 33.9
  L1 w0.116: v4(185.44,184.44) U1.AE22@185.927,184.927 ; U10.F4@190.127,207.448 v2(190.53,207.044)
  L12 (Sign) w0.092: v4(185.44,184.44) 185.905,184.44 186.276,184.81 187.536,184.81 187.953,185.227 187.953,185.652 186.953,186.652 186.953,188.716 184.96,190.709 184.96,190.892 184.949,190.903 184.949,192.195 184.96,192.206 184.96,193.021 194.28,202.341 194.28,205.287 194.044,205.523 194.044,205.585 193.856,205.773 193.554,205.773 192.1,207.226 190.712,207.226 v2(190.53,207.044)
DDR4_DQ18: U1.AF22 U10.H3 | length 32
  L1 w0.116: U1.AF22@186.927,184.927 v4(187.414,184.44) ; U10.H3@193.327,209.048 v2(193.73,209.452)
  L12 (Sign) w0.092: v4(187.414,184.44) 187.437,184.44 188.145,185.148 188.145,185.732 187.145,186.732 187.145,188.796 185.152,190.789 185.152,190.971 185.141,190.983 185.141,192.115 185.152,192.127 185.152,192.941 194.526,202.315 194.526,205.549 193.73,206.345 v2(193.73,209.452)
DDR4_DQ19: U1.AG21 U10.H4 | length 38.2
  L1 w0.116: v4(187.44,183.44) U1.AG21@187.927,183.927 ; v2(189.723,208.644) U10.H4@190.127,209.048
  L12 (Sign) w0.092: v4(187.44,183.44) 187.569,183.569 187.569,183.598 187.705,183.735 187.706,183.735 188.119,184.148 188.119,184.149 188.721,184.75 188.721,185.97 187.721,186.97 187.721,190.561 188.316,191.156 188.316,192.985 196.101,200.77 196.101,208.09 195.143,209.048 194.342,209.048 194.101,209.289 194.101,209.594 193.892,209.803 193.607,209.803 193.327,209.523 193.327,209.227 192.744,208.644 v2(189.723,208.644)
DDR4_DQ20: U1.AD20 U10.H2 | length 36.7
  L1 w0.116: v10(184.44,182.44) U1.AD20@184.927,182.927 ; U10.H2@194.127,209.048 v2(194.53,209.452)
  L12 (Sign) w0.092: v10(184.44,182.44) 185.044,183.044 187.628,183.044 187.784,183.2 187.784,183.543 187.786,183.543 188.311,184.068 188.311,184.07 188.913,184.671 188.913,186.087 187.913,187.087 187.913,190.482 188.57,191.139 188.57,192.968 196.469,200.867 196.469,207.994 195.011,209.452 v2(194.53,209.452)
DDR4_DQ21: U1.AF20 U10.H5 | length 35.8
  L1 w0.116: v4(186.44,182.44) U1.AF20@186.927,182.927 ; v2(188.923,208.644) U10.H5@189.327,209.048
  L12 (Sign) w0.092: v4(186.44,182.44) 186.186,182.186 185.915,182.186 185.77,182.042 183.277,182.042 183.044,182.276 183.044,186.604 183.045,186.606 183.045,188.615 182.78,188.88 182.78,194.065 186.679,197.964 186.679,208.581 187.33,209.232 188.54,209.232 188.923,208.85 v2(188.923,208.644)
DDR4_DQ22: U1.AE20 U10.J3 | length 38.5
  L1 w0.116: v4(185.44,182.44) U1.AE20@185.927,182.927 ; v2(192.923,209.444) U10.J3@193.327,209.848
  L12 (Sign) w0.092: v4(185.44,182.44) 185.791,182.791 187.647,182.791 188.008,183.152 188.008,183.487 189.105,184.584 189.105,186.27 188.105,187.27 188.105,190.376 188.927,191.199 188.927,192.178 196.952,200.203 196.952,207.782 194.886,209.848 194.241,209.848 194.094,209.994 193.473,209.994 v2(192.923,209.444)
DDR4_DQ23: U1.AG20 U10.J4 | length 39
  L1 w0.116: v4(187.44,182.44) U1.AG20@187.927,182.927 ; v2(189.723,209.444) U10.J4@190.127,209.848
  L12 (Sign) w0.092: v4(187.44,182.44) 186.991,181.991 185.991,181.991 185.839,181.839 183.172,181.839 182.829,182.181 182.829,183.596 182.119,184.307 182.119,184.573 182.852,185.306 182.852,186.683 182.853,186.685 182.853,188.535 182.588,188.801 182.588,194.145 186.487,198.044 186.487,208.661 187.674,209.848 189.32,209.848 v2(189.723,209.444)
DDR4_DQ24: U1.AG23 U10.A3 | length 24
  L1 w0.116: v4(187.44,185.44) U1.AG23@187.927,185.927 ; v2(192.923,203.044) U10.A3@193.327,203.448
  L12 (Sign) w0.092: v4(187.44,185.44) 186.961,185.44 185.761,186.64 185.761,188.547 185.226,189.082 185.226,189.628 184.384,190.471 184.384,190.653 184.373,190.664 184.373,192.433 184.384,192.445 184.384,193.259 192.799,201.674 192.799,202.92 v2(192.923,203.044)
DDR4_DQ25: U1.AF23 U10.B5 | length 25.8
  L1 w0.116: v4(186.44,185.44) U1.AF23@186.927,185.927 ; v2(188.923,204.652) U10.B5@189.327,204.248
  L12 (Sign) w0.092: v4(186.44,185.44) 186.194,185.194 185.753,185.194 185.623,185.064 185.293,185.064 185.014,185.344 184.29,185.344 184.061,185.572 184.061,187.165 183.66,187.566 183.66,190.109 183.616,190.153 183.616,190.335 183.605,190.346 183.605,192.752 183.616,192.763 183.616,193.577 183.66,193.621 183.66,194.13 189.343,199.814 189.343,204.248 188.94,204.652 v2(188.923,204.652)
DDR4_DQ26: U1.AF25 U10.C3 | length 22.7
  L1 w0.116: v4(186.44,188.414) U1.AF25@186.927,187.927 ; v2(192.923,204.644) U10.C3@193.327,205.048
  L12 (Sign) w0.092: v4(186.44,188.414) 186.44,188.686 184.576,190.55 184.576,190.733 184.565,190.744 184.565,192.354 184.576,192.365 184.576,193.18 193.777,202.381 193.777,204.267 193.37,204.673 192.952,204.673 v2(192.923,204.644)
DDR4_DQ27: U1.AE23 U10.C4 | length 24.7
  L1 w0.116: v4(185.44,185.44) U1.AE23@185.927,185.927 ; U10.C4@190.127,205.048 v2(190.53,204.644)
  L12 (Sign) w0.092: v4(185.44,185.44) 185.44,186.556 184.861,187.134 184.861,187.553 184.604,187.81 184.196,187.81 183.852,188.155 183.852,190.188 183.808,190.232 183.808,190.415 183.797,190.426 183.797,192.672 183.808,192.683 183.808,193.498 183.852,193.542 183.852,193.808 191.11,201.066 191.11,204.065 v2(190.53,204.644)
DDR4_DQ28: U1.AC22 U10.C2 | length 31.5
  L1 w0.116: v4(183.44,184.44) U1.AC22@183.927,184.927 ; v2(193.723,205.452) U10.C2@194.127,205.048
  L12 (Sign) w0.092: v4(183.44,184.44) 184.141,185.141 184.713,185.141 184.982,184.872 185.872,184.872 186.002,185.002 187.456,185.002 187.761,185.307 187.761,185.573 186.761,186.573 186.761,188.637 184.768,190.63 184.768,190.812 184.757,190.824 184.757,192.274 184.768,192.286 184.768,193.1 193.992,202.325 193.992,205.184 193.725,205.452 v2(193.723,205.452)
DDR4_DQ29: U1.AC23 U10.C5 | length 24.7
  L1 w0.116: v4(183.44,185.44) U1.AC23@183.927,185.927 ; U10.C5@189.327,205.048 v2(189.73,204.644)
  L12 (Sign) w0.092: v4(183.44,185.44) 183.869,185.869 183.869,186.96 183.632,187.197 183.632,187.323 183.468,187.487 183.468,190.029 183.424,190.073 183.424,190.256 183.413,190.267 183.413,192.831 183.424,192.842 183.424,193.657 183.468,193.701 183.468,194.21 188.252,198.995 188.252,204.773 188.546,205.067 189.308,205.067 v2(189.73,204.644)
DDR4_DQ30: U1.AD25 U10.D3 | length 22
  L1 w0.116: v4(184.44,188.414) U1.AD25@184.927,187.927 ; v2(192.923,205.444) U10.D3@193.327,205.848
  L12 (Sign) w0.092: v4(184.44,188.414) 184.44,190.143 184.192,190.391 184.192,190.574 184.181,190.585 184.181,192.513 184.192,192.524 184.192,193.339 192.375,201.522 192.375,204.896 v2(192.923,205.444)
DDR4_DQ31: U1.AC24 U10.D4 | length 24
  L1 w0.116: v4(183.44,186.44) U1.AC24@183.927,186.927 ; v2(189.723,205.444) U10.D4@190.127,205.848
  L12 (Sign) w0.092: v4(183.44,186.44) 183.44,187.243 183.276,187.407 183.276,188.89 182.972,189.194 182.972,193.986 187.281,198.295 187.281,204.236 188.49,205.444 v2(189.723,205.444)
DDR4_DQ32: U1.U24 U9.G2 | length 24.8
  L1 w0.116: v2(170.802,207.844) U9.G2@171.206,208.248 ; U1.U24@177.927,186.927 v10(178.414,187.414)
  L12 (Sign) w0.092: v2(170.802,207.844) 170.802,207.162 175.056,202.909 175.056,198.718 175.884,197.89 175.884,193.699 176.365,193.218 176.365,191.685 177.508,190.542 177.508,188.321 v10(178.414,187.414)
DDR4_DQ33: U1.V23 U9.F4 | length 27.7
  L1 w0.116: U9.F4@167.206,207.448 v2(167.609,207.044) ; v10(178.44,186.414) U1.V23@178.927,185.927
  L12 (Sign) w0.092: v2(167.609,207.044) 168.223,207.044 169.413,205.854 170.167,205.854 170.562,205.459 171.256,205.459 174.48,202.236 174.48,198.199 175.308,197.371 175.308,193.335 175.741,192.902 175.741,191.66 175.781,191.621 175.781,191.454 176.932,190.303 176.932,188 177.194,187.738 177.194,187.66 177.634,187.22 177.634,187.091 178.091,186.634 178.111,186.634 178.331,186.414 v10(178.44,186.414)
DDR4_DQ34: U1.U25 U9.H3 | length 25.8
  L1 w0.116: v2(170.002,208.644) U9.H3@170.406,209.048 ; U1.U25@177.927,187.927 v10(178.414,188.414)
  L12 (Sign) w0.092: v2(170.002,208.644) 171.217,208.644 171.271,208.591 171.271,207.466 175.248,203.489 175.248,199.048 176.119,198.176 176.119,193.735 176.557,193.297 176.557,191.764 177.521,190.8 177.744,190.8 178.414,190.129 v10(178.414,188.414)
DDR4_DQ35: U1.V24 U9.H4 | length 29.6
  L1 w0.116: U9.H4@167.206,209.048 v2(167.609,208.644) ; U1.V24@178.927,186.927 v10(179.414,186.44)
  L12 (Sign) w0.092: v2(167.609,208.644) 167.609,208.107 169.671,206.046 170.247,206.046 170.642,205.651 171.336,205.651 174.672,202.315 174.672,198.279 175.5,197.451 175.5,193.415 175.933,192.981 175.933,191.74 175.981,191.692 175.981,191.526 177.124,190.383 177.124,190.277 177.124,188.201 177.124,188.103 177.826,187.4 177.826,187.171 178.171,186.826 179.028,186.826 v10(179.414,186.44)
DDR4_DQ36: U1.Y25 U9.H2 | length 25.1
  L1 w0.116: U9.H2@171.206,209.048 v2(171.609,208.644) ; v10(180.44,188.414) U1.Y25@180.927,187.927
  L12 (Sign) w0.092: v2(171.609,208.644) 171.609,207.399 175.44,203.568 175.44,199.941 177.824,197.557 177.824,191.03 v10(180.44,188.414)
DDR4_DQ37: U1.AA23 U9.H5 | length 36.2
  L1 w0.116: v2(166.002,208.644) U9.H5@166.406,209.048 ; U1.AA23@181.927,185.927 v10(182.414,186.414)
  L12 (Sign) w0.092: v2@166.002,208.645 166.002,209.067 166.481,209.547 166.481,209.577 166.669,209.765 166.7,209.765 166.782,209.848 170.733,209.848 171.385,209.196 172.129,209.196 172.404,208.921 172.404,208.177 175.981,204.6 175.981,199.998 178.473,197.506 178.473,192.85 178.649,192.673 178.698,192.673 178.698,192.307 178.44,192.049 178.44,191.529 178.662,191.306 178.662,191.182 179.86,189.984 180.425,189.984 180.894,189.515 181.171,189.515 181.515,189.171 181.515,188.894 181.724,188.685 181.724,187.57 182.414,186.88 v10(182.414,186.414)
DDR4_DQ38: U1.AA25 U9.J3 | length 29.8
  L1 w0.116: U9.J3@170.406,209.848 v2(170.809,210.252) ; U1.AA25@181.927,187.927 v10(182.414,187.44)
  L12 (Sign) w0.092: v2(170.809,210.252) 171.673,209.388 172.209,209.388 172.596,209.001 172.596,208.465 176.173,204.888 176.173,200.077 178.89,197.36 178.89,191.226 179.94,190.176 180.941,190.176 182.414,188.703 v10(182.414,187.44)
DDR4_DQ39: U1.Y23 U9.J4 | length 34.1
  L1 w0.116: v2(166.802,209.444) U9.J4@167.206,209.848 ; U1.Y23@180.927,185.927 v10(181.414,186.414)
  L12 (Sign) w0.092: v2@166.802,209.427 167.225,209.004 172.05,209.004 172.212,208.842 172.212,207.068 175.632,203.648 175.632,200.02 178.141,197.511 178.141,191.227 179.891,189.477 180.661,189.477 180.815,189.323 181.091,189.323 181.323,189.091 181.323,188.815 181.33,188.808 181.33,188.489 180.927,188.086 180.927,187.524 181.414,187.037 v10(181.414,186.414)
  L12 (Sign) w0.1: v2@166.802,209.427 v2(166.802,209.444)
DDR4_DQ40: U1.P23 U9.A3 | length 23.4
  L1 w0.116: v2(170.002,203.044) U9.A3@170.406,203.448 ; U1.P23@174.927,185.927 v10(175.414,186.414)
  L12 (Sign) w0.092: v2(170.002,203.044) 170.002,201.511 173.203,198.31 173.203,193.151 173.248,193.105 173.248,191.052 173.76,190.54 174.014,190.54 174.927,189.627 174.927,188.178 175.273,187.833 175.276,187.836 175.604,187.836 175.629,187.81 176.578,187.81 176.81,187.578 176.81,187.501 177.248,187.063 177.248,186.794 176.868,186.414 v10(175.414,186.414)
DDR4_DQ41: U1.R23 U9.B5 | length 24.3
  L1 w0.116: v2(166.002,203.844) U9.B5@166.406,204.248 ; v10(175.44,185.44) U1.R23@175.927,185.927
  L12 (Sign) w0.092: v2(166.002,203.844) 166.002,201.882 171.883,196.001 171.883,191.449 171.606,191.172 171.606,190.594 172.223,189.977 172.223,189.902 172.569,189.556 172.569,188.733 173.179,188.124 173.179,186.828 173.66,186.347 174.028,186.347 174.936,185.44 v10(175.44,185.44)
DDR4_DQ42: U1.T23 U9.C3 | length 24.2
  L1 w0.116: v2(170.002,204.644) U9.C3@170.406,205.048 ; U1.T23@176.927,185.927 v10(177.414,185.44)
  L12 (Sign) w0.092: v2(170.002,204.644) 170.002,204.064 173.724,200.342 173.724,195.821 174.248,195.297 174.248,190.775 175.552,189.471 175.552,188.849 175.606,188.795 175.606,188.783 175.667,188.722 175.678,188.722 175.756,188.644 175.756,188.633 175.81,188.578 175.81,188.484 176.276,188.018 176.642,188.018 177.002,187.658 177.002,187.58 177.44,187.142 177.44,187.014 177.902,186.553 177.902,185.927 v10(177.414,185.44)
DDR4_DQ43: U1.P26 U9.C4 | length 19.6
  L1 w0.116: U9.C4@167.206,205.048 v2(167.609,204.644) ; v10(174.44,189.414) U1.P26@174.927,188.927
  L12 (Sign) w0.092: v2(167.609,204.644) 168.631,203.623 168.631,200.279 172.606,196.304 172.606,191.794 172.799,191.601 172.799,190.601 173.986,189.414 v10(174.44,189.414)
DDR4_DQ44: U1.T25 U9.C2 | length 19.8
  L1 w0.116: v2(170.802,204.644) U9.C2@171.206,205.048 ; v10(176.44,188.414) U1.T25@176.927,187.927
  L12 (Sign) w0.092: v2(170.802,204.644) 173.916,201.531 173.916,196.49 174.44,195.967 174.44,190.926 176.44,188.927 v10(176.44,188.414)
DDR4_DQ45: U1.U23 U9.C5 | length 28.9
  L1 w0.116: v2(166.002,204.644) U9.C5@166.406,205.048 ; v10(177.44,186.414) U1.U23@177.927,185.927
  L12 (Sign) w0.092: v2(166.002,204.644) 166.002,204.293 165.875,204.165 165.869,204.165 165.681,203.977 165.681,203.972 165.481,203.772 165.481,202.095 171.691,195.885 171.691,191.618 171.399,191.326 171.399,190.455 172.377,189.477 172.377,188.608 172.987,187.998 172.987,186.169 173.749,185.407 174.407,185.407 174.89,184.925 175.95,184.925 v10(177.44,186.414)
DDR4_DQ46: U1.T26 U9.D3 | length 20.5
  L1 w0.116: v2(170.002,205.444) U9.D3@170.406,205.848 ; v10(176.44,189.414) U1.T26@176.927,188.927
  L12 (Sign) w0.092: v2(170.002,205.444) 170.012,205.435 170.315,205.435 170.483,205.267 171.177,205.267 174.288,202.156 174.288,196.861 174.927,196.222 174.927,190.927 v10(176.44,189.414)
DDR4_DQ47: U1.P24 U9.D4 | length 23.2
  L1 w0.116: U9.D4@167.206,205.848 v2(167.609,205.444) ; v10(174.44,187.414) U1.P24@174.927,186.927
  L12 (Sign) w0.092: v2(167.609,205.444) 166.84,204.675 166.84,201.587 172.328,196.099 172.328,191.456 172.607,191.176 172.607,190.521 173.563,189.566 173.563,187.587 173.735,187.414 v10(174.44,187.414)
DDR4_DQ48: U1.U26 U11.G2 | length 22.8
  L1 w0.116: v6(177.44,189.414) U1.U26@177.927,188.927 ; U11.G2@182.666,208.248 v6(183.07,207.844)
  L3 (Sign) w0.092: v6(177.44,189.414) 177.444,189.419 177.444,190.843 176.531,191.756 176.531,192.091 177.511,193.071 177.511,193.843 182.666,198.998 182.666,206.648 183.07,207.052 v6(183.07,207.844)
DDR4_DQ49: U1.V26 U11.F4 | length 26.9
  L1 w0.116: U11.F4@178.666,207.448 179.063,207.052 v6(179.063,207.049) ; U1.V26@178.927,188.927 v6(179.414,189.414)
  L3 (Sign) w0.092: v6(179.063,207.049) 180.324,207.049 182.084,205.288 182.084,198.985 177.127,194.027 177.127,193.23 176.147,192.25 176.147,191.526 177.06,190.612 177.06,189.761 176.927,189.627 176.927,189.202 177.305,188.824 177.965,188.824 178.206,189.065 179.065,189.065 v6(179.414,189.414)
DDR4_DQ50: U1.U28 U11.H3 | length 24.7
  L1 w0.116: U1.U28@177.927,190.927 v6(178.414,190.44) ; U11.H3@181.866,209.048 v6(182.27,209.452)
  L3 (Sign) w0.092: v6(178.414,190.44) 178.927,190.952 178.927,191.436 179.763,192.272 179.763,193.217 180.281,193.735 180.748,193.735 184.571,197.558 184.571,208.258 183.377,209.452 v6(182.27,209.452)
DDR4_DQ51: U1.V27 U11.H4 | length 26.4
  L1 w0.116: v6(178.44,189.44) U1.V27@178.927,189.927 ; U11.H4@178.666,209.048 v6(179.07,208.644)
  L3 (Sign) w0.092: v6(178.44,189.44) 178.32,189.32 177.965,189.32 177.738,189.093 177.307,189.093 177.119,189.281 177.119,189.547 177.252,189.681 177.252,190.692 176.339,191.605 176.339,192.171 177.319,193.15 177.319,193.948 182.276,198.905 182.276,205.438 v6(179.07,208.644)
DDR4_DQ52: U1.U30 U11.H2 | length 20.4
  L1 w0.116: U1.U30@177.927,192.927 v6(178.414,193.414) ; U11.H2@182.666,209.048 v6(183.07,208.644)
  L3 (Sign) w0.092: v6(178.414,193.414) 178.72,193.414 179.041,193.735 179.464,193.735 179.848,194.119 180.513,194.119 184.175,197.782 184.175,208.013 183.544,208.644 v6(183.07,208.644)
DDR4_DQ53: U1.V30 U11.H5 | length 26.2
  L1 w0.116: v6(177.463,209.452) U11.H5@177.866,209.048 ; U1.V30@178.927,192.927 v6(179.414,193.414)
  L3 (Sign) w0.092: v6(177.463,209.452) 177.811,209.8 180.522,209.8 181.278,209.043 183.514,209.043 184.379,208.178 184.379,197.714 180.592,193.927 179.927,193.927 v6(179.414,193.414)
DDR4_DQ54: U1.W30 U11.J3 | length 22.2
  L1 w0.116: U1.W30@179.927,192.927 v6(180.414,193.414) ; v6(181.463,209.444) U11.J3@181.866,209.848
  L3 (Sign) w0.092: v6(180.414,193.414) 180.443,193.443 180.727,193.443 184.763,197.478 184.763,208.337 183.328,209.773 181.791,209.773 v6(181.463,209.444)
DDR4_DQ55: U1.W29 U11.J4 | length 27.3
  L1 w0.116: v6(178.263,209.444) U11.J4@178.666,209.848 ; v6(179.44,192.414) U1.W29@179.927,191.927
  L3 (Sign) w0.092: v6(178.263,209.444) 178.308,209.399 180.631,209.399 181.178,208.851 182.224,208.851 182.828,208.248 183.534,208.248 183.967,207.816 183.967,197.845 180.534,194.412 179.869,194.412 179.384,193.927 178.962,193.927 178.77,193.735 178.703,193.735 178.281,193.735 178.087,193.541 178.087,193.211 178.204,193.093 178.761,193.093 v6(179.44,192.414)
